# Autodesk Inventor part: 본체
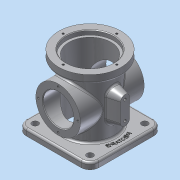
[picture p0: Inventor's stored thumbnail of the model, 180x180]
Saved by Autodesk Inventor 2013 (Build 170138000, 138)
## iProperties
Created: 2021-03
Part Number: 본체
Material: 알루미늄 6061
Document SubType Name: Modeling
Designer: Administrator
Mass: 822.758 g
Surface Area: 856.472 cm^2
Volume: 303.601 cm^3
Density: 2.71 g/cm^3
Author: Administrator
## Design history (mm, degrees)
sketch "스케치1"
  geometry: L1 (57, -57)-(-57, -57); L2 (-57, -57)-(-57, 57); L3 (-57, 57)-(57, 57); L4 (57, 57)-(57, -57); L5 (57, -57)-(-57, 57); L6 (-57, -57)-(57, 57); 1 further point
  constraints: 12 end point, 2 midpoint, 2 parallel, 2 perpendicular, 1 horizontal
  dimensions: "d0" = 114 distance of L2.end L3.end
extrude "돌출1" new body sketch "스케치1" distance "d2" = 10; taper "d3" = 0 deg
sketch "스케치2"
  geometry: C1 r 38 at (0, 0); 1 further point
  constraints: 1 centre point, 1 coincident
  dimensions: "d4" = 76 diameter of C1
extrude "돌출2" join sketch "스케치2" distance "d6" = 88; taper "d7" = 0 deg
sketch "스케치3"
  geometry: C1 r 38 at (0, 0) reference; C2 r 49 at (0, 0)
  constraints: 1 centre point, 1 coincident
  dimensions: "d8" = 98 diameter of C2
extrude "돌출3" join sketch "스케치3" distance "d10" = 13; taper "d11" = 0 deg
sketch "스케치4"
  geometry: C1 r 38 at (0, 0) reference
extrude "돌출4" join sketch "스케치4" distance "d12" = 13; taper "d13" = 0 deg
fillet "모깎기1" dims "d14" = 14
sketch "스케치5"
  geometry: L1 (-43, 0)-(43, 0) reference; C1 r 35 at (0, 54); 1 further point
  constraints: 1 centre point, 1 vertical alignment
  dimensions: "d15" = 54 distance from line of L1 C1.centre; "d16" = 70 diameter of C1
extrude "돌출5" join sketch "스케치5" stored distance "d17" = 100; taper "d18" = 0 deg
node "작업 평면2"
sketch "스케치7"
  geometry: L1 (-7, 70)-(-7, 41); L2 (7, 70)-(7, 41); L3 (-43, 0)-(43, 0) reference; A1 r 7 centre (0, 70) between (-7, 70) and (7, 70); A2 r 7 centre (0, 41) between (-7, 41) and (7, 41); 1 further point
  constraints: 4 end point, 4 point on circle, 4 tangent, 2 centre point, 2 vertical alignment
  dimensions: "d29" = 14 diameter of A1; "d31" = 43 dimension on A2 A1; "d32" = 14 diameter of A2; "d34" = 41 distance from line of L3 A2.centre
extrude "돌출7" join sketch "스케치7" stored distance "d35" = 98; taper "d36" = 15 deg
sketch "스케치8"
  geometry: C1 r 35 at (0, 0) reference; C2 r 24 at (0, 0); 1 further point
  constraints: 1 centre point, 1 coincident
  dimensions: "d37" = 48 diameter of C2
extrude "돌출8" cut sketch "스케치8" stored distance "d39" = 98; taper "d40" = 0 deg
hole "구멍1" diameter "d43" = 66; stored, may be unused: countersink angle "d47" = 90 deg, drill point angle "d49" = 118 deg; dims "d41" = 10, "d42" = 10, "d44" = 6, "d45" = 74, "d46" = 7, "d48" = 8
sketch "스케치9"
  geometry: C1 r 37 at (0, 0) reference; C2 r 49 at (0, 0) reference; A1 r 42 centre (0, 0) between (-42, 0) and (0, 42); 2 further points
  constraints: 4 point on circle, 2 horizontal alignment, 2 vertical alignment, 1 centre point, 1 coincident
  dimensions: "d50" = 84 diameter of A1
hole "구멍2" sketch "스케치9" at (-42, 0), (0, 42), (0, -42), (42, 0) diameter "d52" = 3.242; stored, may be unused: countersink angle "d56" = 90 deg, drill point angle "d58" = 118 deg; dims "d53" = 6, "d54" = 74, "d55" = 7, "d57" = 8
sketch "스케치10"
  geometry: C1 r 24 at (0, 0) reference; C2 r 35 at (0, 0) reference; A1 r 31 centre (0, 0) between (0, 31) and (31, 0); 3 further points
  constraints: 4 point on circle, 2 horizontal alignment, 2 vertical alignment, 1 centre point, 1 coincident
  dimensions: "d59" = 62 diameter of A1
hole "구멍3" sketch "스케치10" at (0, 31), (31, 0), (-31, 0), (0, -31) diameter "d61" = 3.242; stored, may be unused: countersink angle "d65" = 90 deg, drill point angle "d67" = 118 deg; dims "d62" = 6, "d63" = 74, "d64" = 7, "d66" = 8
hole "구멍4" diameter "d70" = 4.134; stored, may be unused: countersink angle "d74" = 90 deg, drill point angle "d76" = 118 deg; dims "d68" = 10, "d69" = 10, "d71" = 8, "d72" = 74, "d73" = 7, "d75" = 10
hole "구멍5" diameter "d79" = 4.134; stored, may be unused: countersink angle "d83" = 90 deg, drill point angle "d85" = 118 deg; dims "d77" = 10, "d78" = 10, "d80" = 8, "d81" = 74, "d82" = 7, "d84" = 10
fillet "모깎기2" dims "d86" = 3
fillet "모깎기3" dims "d87" = 3
fillet "모깎기4" dims "d88" = 3
fillet "모깎기5" dims "d89" = 3
fillet "모깎기6" dims "d90" = 3
chamfer "모따기1" distance "d91" = 1; stored, may be unused: second distance "d92" = 2, angle "d93" = 45 deg
hole "구멍6" diameter "d96" = 10; stored, may be unused: countersink angle "d100" = 90 deg, drill point angle "d102" = 118 deg; dims "d94" = 10, "d95" = 10, "d97" = 8, "d98" = 74, "d99" = 7, "d101" = 10
hole "구멍7" diameter "d105" = 10; stored, may be unused: countersink angle "d109" = 90 deg, drill point angle "d111" = 118 deg; dims "d103" = 10, "d104" = 10, "d106" = 8, "d107" = 74, "d108" = 7, "d110" = 10
hole "구멍8" diameter "d114" = 10; stored, may be unused: countersink angle "d118" = 90 deg, drill point angle "d120" = 118 deg; dims "d112" = 10, "d113" = 10, "d115" = 8, "d116" = 74, "d117" = 7, "d119" = 10
hole "구멍9" diameter "d123" = 10; stored, may be unused: countersink angle "d127" = 90 deg, drill point angle "d129" = 118 deg; dims "d121" = 10, "d122" = 10, "d124" = 8, "d125" = 74, "d126" = 7, "d128" = 10
sketch "스케치11"
  geometry: L1 (71.368, 0)-(-86.916, 0); C1 r 41 at (0, 0) reference; C2 r 50 at (0, 0)
  constraints: 2 end point, 1 centre point, 1 coincident, 1 other
  dimensions: "d130" = 100 diameter of C2
feature "엠보싱1" sketch "스케치11" dims "d0" = 114, "d132" = 0.5, "d133" = 0
node "솔리드1"
mirror "대칭1"
node "작업 평면3"
other parameters: "d19" = 55
